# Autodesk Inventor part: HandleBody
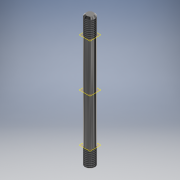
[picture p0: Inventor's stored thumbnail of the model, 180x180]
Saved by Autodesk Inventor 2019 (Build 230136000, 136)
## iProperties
Created: 2011-02
Part Number: HandleBody
Material: Generic
Document SubType Name: Modeling
Designer: landrews
Density: 1 g/cm^3
Appearance: Knurled 45
Mass: 2.24519 g
Surface Area: 15.3983 cm^2
Volume: 2.24519 cm^3
Author: landrews
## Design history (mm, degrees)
sketch "Sketch1"
  geometry: C1 r 3 at (0, 0); 1 further point
  constraints: 1 centre point, 1 coincident
  dimensions: "d0" = 6 diameter of C1
extrude "Extrusion1" new body sketch "Sketch1" stored distance "d1" = 80; taper "d2" = 0 deg
chamfer "Chamfer2" distance "d10" = 1; stored, may be unused: second distance "d11" = 2, angle "d12" = 45 deg
thread "Thread1" dims "d13" = 10, "d14" = 0
thread "Thread2" dims "d15" = 10, "d16" = 0
workplane "Work Plane5"
workplane "Work Plane6"
body "Solid1"
other parameters: "d18" = 29, "d19" = -29
